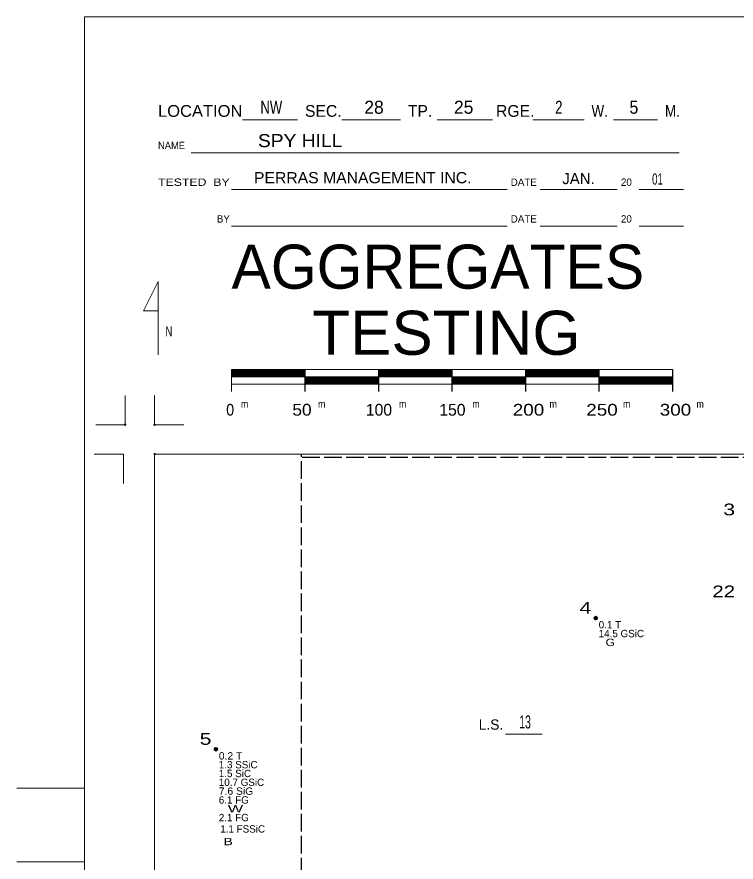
# Model space of a CAD drawing. Extents: x -496 to 480, y -450 to 700.
# Drawn here: x -496 to -7, y 125 to 700 of the extents above; entities that cross this region are included whole.
import ezdxf
from ezdxf.enums import TextEntityAlignment as Align

# ---------------------------------------------------------------- set-up
doc = ezdxf.new("R2010")
doc.units = 0
doc.header["$LTSCALE"] = 2
doc.header["$PDMODE"] = 32
doc.header["$PDSIZE"] = 1
doc.linetypes.add('LONG_DASHED', pattern=[7.5, 6, -1.5])
doc.layers.add('1', color=7, linetype='Continuous', lineweight=13)
doc.layers.add('2', color=7, linetype='Continuous', lineweight=35)

msp = doc.modelspace()

# ---------------------------------------------------------------- linework, layer by layer
at = {"layer": '1'}
for p, q in [((-342.517, 629.973), (-305.017, 629.973)), ((-275.017, 629.973), (-235.017, 629.973)), ((-210.017, 629.973), (-172.517, 629.973)), ((-145.017, 629.973), (-110.017, 629.973)), ((-90.017, 629.973), (-60.017, 629.973)), ((-377.517, 607.473), (-45.359, 607.473)), ((-350.017, 582.473), (-162.517, 582.473)), ((-140.017, 582.473), (-87.517, 582.473)), ((-72.517, 582.473), (-42.517, 582.473)), ((-350.017, 557.473), (-162.517, 557.473)), ((-140.017, 557.473), (-87.517, 557.473)), ((-72.517, 557.473), (-42.517, 557.473)), ((-350.017, 459.973), (-350.017, 444.973)), ((-50.017, 459.973), (-350.017, 459.973)), ((-350.017, 454.973), (-50.017, 454.973)), ((-422.391, 422.339), (-422.391, 442.339)), ((-402.391, 422.339), (-402.391, 442.339)), ((-422.391, 422.339), (-442.391, 422.339)), ((-423.537, 402.339), (-443.537, 402.339)), ((-423.537, 402.339), (-423.537, 382.339)), ((-402.391, 402.339), (-402.391, -402.333)), ((-382.391, 402.339), (-402.391, 402.339)), ((-163.533, 211.85), (-138.533, 211.85)), ((-450.017, 174.973), (-496.057, 174.973)), ((-450.017, 124.973), (-496.057, 124.973))]:
    msp.add_line(p, q, dxfattribs=at)
at = {"layer": '1', "lineweight": 25}
for p, q in [((-350.017, 459.473), (-300.017, 459.473)), ((-350.017, 458.973), (-300.017, 458.973)), ((-350.017, 458.473), (-300.017, 458.473)), ((-350.017, 457.973), (-300.017, 457.973)), ((-350.017, 457.473), (-300.017, 457.473)), ((-350.017, 456.973), (-300.017, 456.973)), ((-350.017, 456.473), (-300.017, 456.473)), ((-350.017, 456.473), (-300.017, 456.473)), ((-350.017, 456.473), (-300.017, 456.473)), ((-350.017, 455.973), (-300.017, 455.973)), ((-350.017, 455.973), (-300.017, 455.973)), ((-350.017, 455.473), (-300.017, 455.473)), ((-300.017, 459.973), (-300.017, 444.973)), ((-300.017, 454.473), (-250.017, 454.473)), ((-250.017, 459.973), (-250.017, 444.973)), ((-250.017, 459.473), (-200.017, 459.473)), ((-250.017, 458.973), (-200.017, 458.973)), ((-250.017, 458.473), (-200.017, 458.473)), ((-250.017, 457.973), (-200.017, 457.973)), ((-250.017, 457.473), (-200.017, 457.473)), ((-250.017, 456.973), (-200.017, 456.973)), ((-250.017, 456.473), (-200.017, 456.473)), ((-250.017, 455.973), (-200.017, 455.973)), ((-250.017, 455.473), (-200.017, 455.473)), ((-200.017, 459.973), (-200.017, 444.973)), ((-200.017, 454.473), (-150.017, 454.473)), ((-150.017, 459.973), (-150.017, 444.973)), ((-150.017, 459.473), (-100.017, 459.473)), ((-150.017, 458.973), (-100.017, 458.973)), ((-150.017, 458.473), (-100.017, 458.473)), ((-150.017, 457.973), (-100.017, 457.973)), ((-150.017, 457.473), (-100.017, 457.473)), ((-150.017, 456.973), (-100.017, 456.973)), ((-150.017, 456.473), (-100.017, 456.473)), ((-150.017, 455.973), (-100.017, 455.973)), ((-150.017, 455.473), (-100.017, 455.473)), ((-100.017, 459.973), (-100.017, 444.973)), ((-100.017, 454.473), (-50.017, 454.473)), ((-50.017, 459.973), (-50.017, 444.973)), ((-300.017, 453.973), (-250.017, 453.973)), ((-300.017, 453.473), (-250.017, 453.473)), ((-300.017, 452.973), (-250.017, 452.973)), ((-300.017, 452.473), (-250.017, 452.473)), ((-300.017, 451.973), (-250.017, 451.973)), ((-300.017, 451.473), (-250.017, 451.473)), ((-300.017, 450.973), (-250.017, 450.973)), ((-300.017, 450.473), (-250.017, 450.473)), ((-200.017, 453.973), (-150.017, 453.973)), ((-200.017, 453.473), (-150.017, 453.473)), ((-200.017, 452.973), (-150.017, 452.973)), ((-200.017, 452.473), (-150.017, 452.473)), ((-200.017, 451.973), (-150.017, 451.973)), ((-200.017, 451.473), (-150.017, 451.473)), ((-200.017, 450.973), (-150.017, 450.973)), ((-200.017, 450.473), (-150.017, 450.473)), ((-100.017, 453.973), (-50.017, 453.973)), ((-100.017, 453.473), (-50.017, 453.473)), ((-100.017, 452.973), (-50.017, 452.973)), ((-100.017, 452.473), (-50.017, 452.473)), ((-100.017, 451.973), (-50.017, 451.973)), ((-100.017, 451.473), (-50.017, 451.473)), ((-100.017, 450.973), (-50.017, 450.973)), ((-100.017, 450.473), (-50.017, 450.473))]:
    msp.add_line(p, q, dxfattribs=at)
at = {"layer": '1'}
for points in [[(449.983, -450.027), (449.983, 399.973), (449.983, 699.973), (-450.017, 699.973), (-450.017, 49.973), (-450.017, -450.027)], [(-400.017, 469.973), (-400.017, 519.973), (-410.017, 499.973), (-400.017, 499.973)], [(-350.017, 449.973), (-50.017, 449.973), (-50.017, 459.973)], [(-402.391, 422.339), (-382.391, 422.339), (-402.391, 422.339)], [(402.281, -402.333), (402.281, 402.339), (-402.391, 402.339)]]:
    msp.add_lwpolyline(points, dxfattribs=at)
for p in [(-422.391, 422.339), (-402.391, 422.339), (-402.391, 402.339)]:
    msp.add_point(p, dxfattribs=at)
at = {"layer": '2', "linetype": 'LONG_DASHED', "lineweight": 25}
msp.add_line((-302.391, -139.499), (-302.391, 402.339), dxfattribs=at)
msp.add_lwpolyline([(400, -400), (400, 400), (-302.391, 400)], dxfattribs=at)
at = {"layer": '2'}
for centre in [(-102.135, 290.769), (-360.654, 201.513)]:
    msp.add_circle(centre, 1, dxfattribs=at)
for points in [[(-102.146, 291.656), (-101.416, 291.252), (-101.264, 290.403), (-101.949, 289.875), (-102.758, 290.106), (-103.045, 290.864), (-102.798, 291.426), (-102.225, 291.594), (-101.551, 291.1), (-101.567, 290.358), (-102.084, 290.1), (-102.607, 290.269), (-102.831, 290.915), (-102.247, 291.381), (-101.809, 290.847), (-101.848, 290.364), (-102.477, 290.499), (-102.331, 291.134), (-102.039, 290.583)], [(-360.665, 202.4), (-359.935, 201.996), (-359.783, 201.147), (-360.468, 200.619), (-361.277, 200.85), (-361.564, 201.608), (-361.317, 202.17), (-360.744, 202.338), (-360.07, 201.844), (-360.086, 201.102), (-360.603, 200.844), (-361.126, 201.013), (-361.35, 201.659), (-360.766, 202.125), (-360.328, 201.591), (-360.367, 201.108), (-360.996, 201.243), (-360.85, 201.878), (-360.558, 201.327)]]:
    msp.add_spline(points, degree=3, dxfattribs=at)

# ---------------------------------------------------------------- texts
at = {"layer": '1'}
for s, height, width, p in [('LOCATION', 8, 1.05, (-400.017, 631.973)), ('W.', 8, 0.85, (-105.017, 631.973)), ('M.', 8, 0.85, (-55.017, 631.973)), ('NAME', 5, 0.95, (-400.017, 609.973)), ('TESTED  BY', 5, 1.25, (-400.017, 584.973)), ('TESTING', 30, 1.05, (-295.017, 469.973)), ('N', 7, 0.7, (-395.017, 482.473)), ('m', 5, 0.9, (-343.607, 434.073)), ('m', 5, 0.9, (-291.107, 434.073)), ('m', 5, 0.9, (-236.107, 434.073)), ('m', 5, 0.9, (-186.107, 434.073)), ('m', 5, 0.9, (-133.607, 434.073)), ('m', 5, 0.9, (-83.607, 434.073)), ('m', 5, 0.9, (-33.607, 434.073)), ('0', 8, 0.9, (-353.607, 428.573)), ('50', 8, 1.1, (-308.607, 428.573)), ('200', 8, 1.2, (-158.607, 428.573)), ('250', 8, 1.2, (-108.607, 428.573)), ('300', 8, 1.2, (-58.607, 428.573))]:
    msp.add_text(s, height=height, dxfattribs=dict(at, width=width)).set_placement(p)
for s, height, width, p in [('NW', 8.89, 0.75, (-322.943, 634.038)), ('2', 8.89, 0.75, (-127.28, 634.037)), ('5', 8.89, 0.9, (-76.181, 634.038)), ('SPY HILL', 8.89, 1.1, (-303.323, 611.329)), ('PERRAS MANAGEMENT INC.', 7.62, 1.05, (-260.682, 586.728)), ('01', 7.62, 0.65, (-60.119, 585.781)), ('13', 8.89, 0.6, (-150.235, 215.639))]:
    msp.add_text(s, height=height, dxfattribs=dict(at, width=width)).set_placement(p, align=Align.CENTER)
for s, height, p in [('SEC.', 8, (-300.017, 631.973)), ('TP.', 8, (-230.017, 631.973)), ('RGE.', 8, (-170.017, 631.973)), ('DATE', 5, (-160.017, 584.973)), ('20', 5, (-85.017, 584.973)), ('BY', 5, (-360.017, 559.973)), ('DATE', 5, (-160.017, 559.973)), ('20', 5, (-85.017, 559.973)), ('AGGREGATES', 30, (-350.017, 514.973)), ('100', 8, (-258.607, 428.573)), ('150', 8, (-208.607, 428.573))]:
    msp.add_text(s, height=height, dxfattribs=at).set_placement(p)
for s, height, p in [('28', 8.89, (-253.021, 634.038)), ('25', 8.89, (-192.027, 634.038)), ('JAN.', 7.62, (-113.875, 586.148)), ('L.S.', 7, (-173.44, 214.794))]:
    msp.add_text(s, height=height, dxfattribs=at).set_placement(p, align=Align.CENTER)
at = {"layer": '2'}
for s, width, p in [('  3', 1.35, (-7.318, 360.711)), (' 22', 1.3, (-7.318, 304.926)), ('  4', 1.35, (-105.136, 293.769)), ('  5', 1.35, (-363.655, 204.513))]:
    msp.add_text(s, height=8, dxfattribs=dict(at, width=width)).set_placement(p, align=Align.RIGHT)
for s, p in [('0.1 T      ', (-100.135, 283.769)), ('14.5 GSiC  ', (-100.135, 277.769)), ('1.3 SSiC   ', (-358.654, 188.513)), ('1.5 SiC    ', (-358.654, 182.513)), ('10.7 GSiC  ', (-358.654, 176.513)), ('6.1 FG     ', (-358.654, 164.513)), ('2.1 FG     ', (-358.654, 152.513)), ('1.1 FSSiC  ', (-357.661, 144.781))]:
    msp.add_text(s, height=5, dxfattribs=at).set_placement(p)
for s, width, p in [('  G        ', 1.25, (-100.135, 271.769)), ('0.2 T      ', 1.05, (-358.654, 194.513)), ('7.6 SiG    ', 1.05, (-358.654, 170.513)), ('  W        ', 1.65, (-358.654, 158.513)), ('  B        ', 1.4, (-360.588, 136.166))]:
    msp.add_text(s, height=5, dxfattribs=dict(at, width=width)).set_placement(p)

doc.saveas('drawing.dxf')
